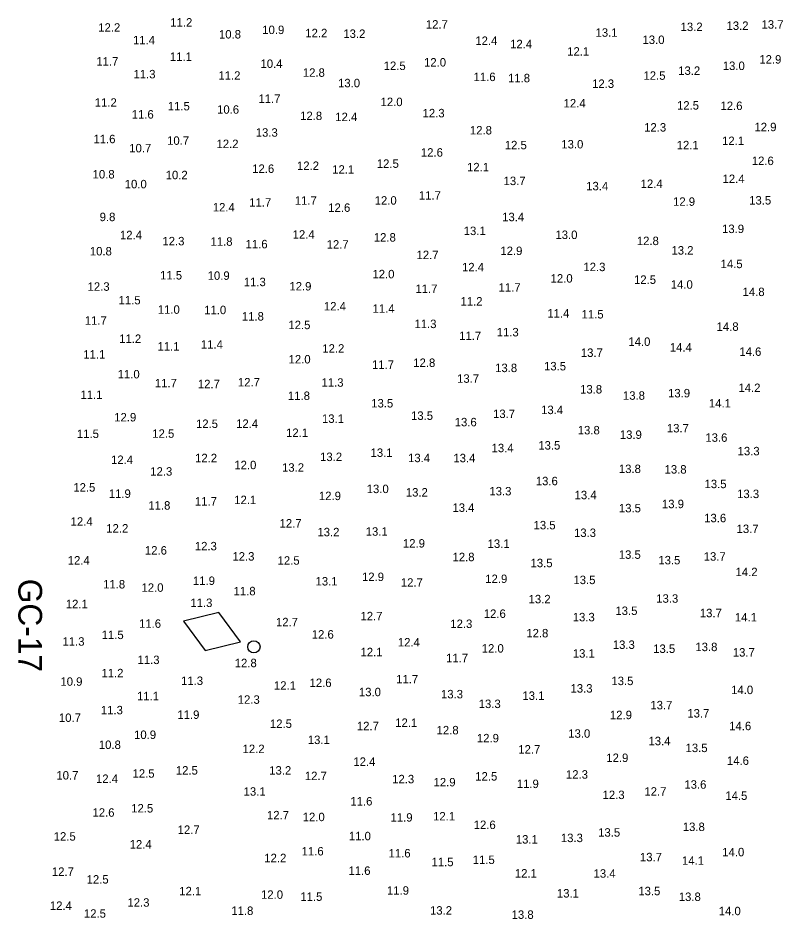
# Model space of a CAD drawing. Extents: x 1023796 to 1112670, y 656573 to 837340.
# Drawn here: x 1109618 to 1110070, y 667529 to 668062 of the extents above; entities that cross this region are included whole.
import ezdxf

# ---------------------------------------------------------------- set-up
doc = ezdxf.new("R2010")
doc.units = 0
doc.layers.add('V-CHAN-NAID', color=7, linetype='Continuous')
doc.layers.add('V-TOPO-SOUN', color=7, linetype='Continuous')

msp = doc.modelspace()

# ---------------------------------------------------------------- linework, layer by layer
at = {"layer": 'V-CHAN-NAID'}
msp.add_lwpolyline([(1109749.49, 667692.55), (1109736.68, 667709.99), (1109715.66, 667704.87), (1109728.47, 667687.43)], close=True, dxfattribs=at)
msp.add_circle((1109757.38, 667689.68), 3.6, dxfattribs=at)

# ---------------------------------------------------------------- texts
msp.add_text('GC-17', height=14, rotation=270, dxfattribs=at).set_placement((1109618.13, 667729.94))
at = {"layer": 'V-TOPO-SOUN'}
for s, p in [('11.2 ', (1109707.94, 668056.45)), ('12.2 ', (1109665.36, 668053.43)), ('10.9 ', (1109762.3, 668052.03)), ('12.7 ', (1109859, 668055.25)), ('13.2 ', (1110009.59, 668053.81)), ('13.2 ', (1110036.74, 668054.49)), ('13.7 ', (1110057.43, 668055.22)), ('11.4 ', (1109685.89, 668045.99)), ('10.8 ', (1109736.72, 668049.41)), ('12.2 ', (1109787.75, 668050.15)), ('13.2 ', (1109810.23, 668049.75)), ('12.4 ', (1109888.25, 668045.6)), ('13.1 ', (1109959.31, 668050.44)), ('13.0 ', (1109987.07, 668046.17)), ('12.4 ', (1109908.82, 668043.64)), ('11.1 ', (1109707.72, 668036.19)), ('12.1 ', (1109942.55, 668039.26)), ('11.7 ', (1109664.22, 668033.38)), ('10.4 ', (1109761.27, 668032.02)), ('12.5 ', (1109834.08, 668030.77)), ('12.0 ', (1109857.93, 668032.84)), ('13.0 ', (1110034.52, 668030.77)), ('12.9 ', (1110056.13, 668034.56)), ('11.3 ', (1109686.17, 668025.83)), ('11.2 ', (1109736.39, 668025.03)), ('12.8 ', (1109786.28, 668026.77)), ('12.5 ', (1109987.64, 668024.99)), ('13.2 ', (1110008.17, 668027.91)), ('13.0 ', (1109807.1, 668020.57)), ('11.6 ', (1109887.21, 668024.23)), ('11.8 ', (1109907.58, 668023.52)), ('12.3 ', (1109957.28, 668020.18)), ('11.2 ', (1109663.28, 668009.06)), ('11.7 ', (1109760.04, 668011.33)), ('12.0 ', (1109832.25, 668009.43)), ('12.4 ', (1109940.45, 668008.64)), ('11.5 ', (1109706.44, 668006.91)), ('10.6 ', (1109735.6, 668004.93)), ('12.5 ', (1110007.46, 668007.36)), ('12.6 ', (1110033.16, 668007.12)), ('11.6 ', (1109685.13, 668002.04)), ('12.8 ', (1109784.68, 668001.18)), ('12.4 ', (1109805.48, 668000.56)), ('12.3 ', (1109857.08, 668002.79)), ('12.8 ', (1109885.05, 667992.66)), ('12.3 ', (1109988.04, 667994.38)), ('12.9 ', (1110053.25, 667994.59)), ('11.6 ', (1109662.51, 667987.49)), ('13.3 ', (1109758.46, 667991.34)), ('10.7 ', (1109683.69, 667982.08)), ('10.7 ', (1109706.05, 667986.55)), ('12.2 ', (1109735.26, 667984.61)), ('12.5 ', (1109905.66, 667983.89)), ('13.0 ', (1109939.08, 667984.4)), ('12.1 ', (1110007.28, 667983.88)), ('12.1 ', (1110034.09, 667986.39)), ('12.6 ', (1109856.07, 667979.54)), ('12.2 ', (1109782.83, 667971.68)), ('12.5 ', (1109830.01, 667972.93)), ('12.6 ', (1110051.66, 667974.57)), ('10.8 ', (1109662.03, 667966.63)), ('10.2 ', (1109705.22, 667966.2)), ('12.6 ', (1109756.36, 667969.93)), ('12.1 ', (1109803.65, 667969.46)), ('12.1 ', (1109883.35, 667970.85)), ('10.0 ', (1109681.01, 667960.82)), ('13.7 ', (1109904.95, 667962.72)), ('12.4 ', (1109985.98, 667961.02)), ('12.4 ', (1110034.38, 667963.94)), ('13.4 ', (1109953.8, 667959.63)), ('11.7 ', (1109754.59, 667949.96)), ('11.7 ', (1109781.53, 667951.07)), ('12.0 ', (1109828.75, 667951.15)), ('11.7 ', (1109854.87, 667954.12)), ('12.9 ', (1110005.13, 667950.47)), ('13.5 ', (1110050.11, 667951.24)), ('12.4 ', (1109733.05, 667947.12)), ('12.6 ', (1109801.33, 667946.91)), ('9.8', (1109666.18, 667941.4)), ('13.4 ', (1109904.11, 667941.39)), ('13.9 ', (1110034.11, 667934.36)), ('12.4 ', (1109678.2, 667930.73)), ('12.4 ', (1109780.27, 667931.03)), ('12.8 ', (1109828.24, 667929.32)), ('13.1 ', (1109881.39, 667933.17)), ('13.0 ', (1109935.61, 667930.84)), ('12.3 ', (1109703.28, 667927.09)), ('11.8 ', (1109731.71, 667926.85)), ('11.6 ', (1109752.45, 667925.34)), ('12.7 ', (1109800.37, 667925.16)), ('12.8 ', (1109983.72, 667927.24)), ('10.8 ', (1109660.37, 667921.13)), ('12.7 ', (1109853.49, 667918.93)), ('12.9 ', (1109903.06, 667921.35)), ('13.2 ', (1110004.2, 667921.64)), ('14.5 ', (1110033.25, 667913.63)), ('12.0 ', (1109827.43, 667907.6)), ('12.4 ', (1109880.37, 667911.72)), ('12.3 ', (1109952.13, 667911.84)), ('11.5 ', (1109701.9, 667906.91)), ('10.9 ', (1109730.03, 667906.71)), ('11.3 ', (1109751.36, 667902.96)), ('12.0 ', (1109932.76, 667905.07)), ('12.5 ', (1109982.06, 667904.33)), ('12.3 ', (1109659.06, 667900.24)), ('12.9 ', (1109778.35, 667900.41)), ('11.7 ', (1109852.85, 667898.93)), ('11.7 ', (1109902, 667899.71)), ('14.0 ', (1110003.77, 667901.45)), ('14.8 ', (1110046.24, 667897.1)), ('11.5 ', (1109677.38, 667892.2)), ('11.2 ', (1109879.5, 667891.51)), ('11.0 ', (1109700.54, 667886.64)), ('11.0 ', (1109727.98, 667886.4)), ('12.4 ', (1109798.74, 667888.59)), ('11.4 ', (1109827.51, 667887.24)), ('11.8 ', (1109750.25, 667882.62)), ('11.4 ', (1109930.82, 667884.4)), ('11.5 ', (1109951.08, 667883.86)), ('11.7 ', (1109657.38, 667880.14)), ('12.5 ', (1109777.75, 667877.54)), ('11.3 ', (1109852.27, 667878.17)), ('14.8 ', (1110030.88, 667876.54)), ('11.7 ', (1109878.7, 667871.08)), ('11.3 ', (1109900.89, 667873.26)), ('11.2 ', (1109677.73, 667869.4)), ('11.1 ', (1109700.36, 667864.87)), ('11.4 ', (1109726.02, 667866)), ('14.0 ', (1109978.71, 667867.66)), ('11.1 ', (1109656.52, 667860.13)), ('12.2 ', (1109797.8, 667863.63)), ('13.7 ', (1109950.63, 667861.11)), ('14.4 ', (1110003.23, 667864.3)), ('14.6 ', (1110044.32, 667861.74)), ('12.0 ', (1109777.88, 667857.26)), ('11.7 ', (1109827.19, 667854.06)), ('12.8 ', (1109851.57, 667855.19)), ('13.8 ', (1109899.96, 667852.14)), ('13.5 ', (1109928.86, 667853.15)), ('11.0 ', (1109676.83, 667848.41)), ('12.7 ', (1109747.91, 667843.66)), ('11.3 ', (1109797.32, 667843.49)), ('13.7 ', (1109877.46, 667845.82)), ('11.7 ', (1109698.83, 667843.12)), ('12.7 ', (1109724.24, 667842.63)), ('13.8 ', (1109950.18, 667839.49)), ('14.2 ', (1110043.78, 667840.36)), ('11.1 ', (1109654.84, 667836.25)), ('11.8 ', (1109777.48, 667835.66)), ('13.8 ', (1109975.5, 667835.79)), ('13.9 ', (1110002.19, 667837.19)), ('13.5 ', (1109826.71, 667831.23)), ('13.4 ', (1109927.14, 667827.31)), ('14.1 ', (1110026.34, 667831.22)), ('12.9 ', (1109674.79, 667822.97)), ('13.1 ', (1109797.61, 667822.12)), ('13.5 ', (1109850.25, 667823.9)), ('13.7 ', (1109898.73, 667824.98)), ('12.5 ', (1109723.13, 667819.1)), ('12.4 ', (1109746.86, 667819.18)), ('13.6 ', (1109876.07, 667820.08)), ('13.7 ', (1110001.47, 667816.48)), ('11.5 ', (1109652.76, 667813.17)), ('12.5 ', (1109697.3, 667813.31)), ('12.1 ', (1109776.38, 667813.78)), ('13.8 ', (1109948.8, 667815.31)), ('13.9 ', (1109973.66, 667812.67)), ('13.5 ', (1109925.49, 667806.32)), ('13.6 ', (1110024.24, 667810.93)), ('13.1 ', (1109826.32, 667802.01)), ('13.4 ', (1109897.85, 667804.78)), ('13.3 ', (1110043.29, 667802.93)), ('12.4 ', (1109672.92, 667797.81)), ('12.2 ', (1109722.59, 667798.86)), ('13.2 ', (1109796.47, 667799.54)), ('13.4 ', (1109848.49, 667798.89)), ('13.4 ', (1109875.28, 667798.83)), ('12.3 ', (1109696.1, 667790.9)), ('12.0 ', (1109745.79, 667794.73)), ('13.2 ', (1109773.99, 667793.24)), ('13.8 ', (1109973.1, 667792.45)), ('13.8 ', (1110000.12, 667792.13)), ('13.6 ', (1109923.99, 667785.23)), ('12.5 ', (1109650.62, 667781.47)), ('13.0 ', (1109824.04, 667780.59)), ('13.3 ', (1109896.57, 667779.23)), ('13.5 ', (1110023.73, 667783.52)), ('11.9 ', (1109671.59, 667777.77)), ('12.1 ', (1109745.74, 667774.07)), ('12.9 ', (1109795.79, 667776.45)), ('13.2 ', (1109847.18, 667778.56)), ('13.4 ', (1109946.93, 667776.97)), ('13.3 ', (1110043, 667777.64)), ('11.8 ', (1109694.97, 667770.82)), ('11.7 ', (1109722.52, 667773.25)), ('13.4 ', (1109874.72, 667769.51)), ('13.5 ', (1109973.12, 667769.22)), ('13.9 ', (1109998.58, 667771.68)), ('13.6 ', (1110023.53, 667763.36)), ('12.4 ', (1109649.03, 667761.3)), ('12.7 ', (1109772.53, 667760.25)), ('13.5 ', (1109922.68, 667759.15)), ('12.2 ', (1109670.11, 667757.28)), ('13.2 ', (1109794.92, 667755.05)), ('13.1 ', (1109823.45, 667755.39)), ('13.3 ', (1109946.58, 667754.64)), ('13.7 ', (1110042.69, 667756.97)), ('12.9 ', (1109845.45, 667748.37)), ('13.1 ', (1109895.51, 667748.17)), ('12.6 ', (1109692.94, 667744.24)), ('12.3 ', (1109722.44, 667746.73)), ('12.4 ', (1109647.32, 667738.36)), ('12.3 ', (1109744.67, 667740.67)), ('12.5 ', (1109771.37, 667738.26)), ('12.8 ', (1109874.78, 667740.33)), ('13.5 ', (1109920.89, 667736.76)), ('13.5 ', (1109973.04, 667741.73)), ('13.5 ', (1109996.44, 667738.45)), ('13.7 ', (1110023.26, 667740.63)), ('14.2 ', (1110042.09, 667731.48)), ('11.9 ', (1109721.33, 667726.28)), ('13.1 ', (1109793.78, 667725.96)), ('12.9 ', (1109821.26, 667728.58)), ('12.9 ', (1109894.12, 667727.41)), ('13.5 ', (1109946.24, 667726.78)), ('11.8 ', (1109668.23, 667724.2)), ('12.0 ', (1109690.91, 667722.22)), ('12.7 ', (1109844.22, 667725.23)), ('11.8 ', (1109745.35, 667720.16)), ('13.2 ', (1109919.74, 667715.42)), ('13.3 ', (1109995.19, 667715.76)), ('12.1 ', (1109646.17, 667712.52)), ('11.3 ', (1109719.81, 667713.22)), ('12.7 ', (1109820.36, 667705.36)), ('12.6 ', (1109893.24, 667706.8)), ('13.3 ', (1109945.84, 667704.77)), ('13.5 ', (1109971.06, 667708.51)), ('13.7 ', (1110020.96, 667707.18)), ('14.1 ', (1110041.71, 667704.68)), ('11.6 ', (1109689.47, 667700.93)), ('12.7 ', (1109770.41, 667701.83)), ('12.3 ', (1109873.47, 667700.81)), ('11.5 ', (1109667.38, 667694.28)), ('12.6 ', (1109791.56, 667694.54)), ('12.8 ', (1109918.4, 667695.27)), ('11.3 ', (1109644.2, 667690.35)), ('12.4 ', (1109842.45, 667689.89)), ('12.1 ', (1109820.39, 667684.11)), ('12.0 ', (1109892.04, 667686.28)), ('13.1 ', (1109945.87, 667683.29)), ('13.3 ', (1109969.51, 667688.45)), ('13.5 ', (1109993.39, 667686.07)), ('13.8 ', (1110018.33, 667687.14)), ('13.7 ', (1110040.45, 667683.93)), ('11.3 ', (1109688.57, 667679.5)), ('11.7 ', (1109870.96, 667680.6)), ('12.8 ', (1109746.02, 667677.65)), ('11.2 ', (1109667.25, 667671.67)), ('11.7 ', (1109841.46, 667668.06)), ('10.9 ', (1109642.99, 667666.66)), ('11.3 ', (1109714.31, 667667.13)), ('12.1 ', (1109769.22, 667664.33)), ('12.6 ', (1109790.26, 667665.93)), ('13.3 ', (1109944.52, 667662.62)), ('13.5 ', (1109968.69, 667667.04)), ('11.1 ', (1109688.26, 667658.09)), ('13.0 ', (1109819.44, 667660.49)), ('13.3 ', (1109867.95, 667659.21)), ('13.1 ', (1109916.08, 667658.31)), ('14.0 ', (1110039.47, 667661.72)), ('12.3 ', (1109747.8, 667656)), ('13.3 ', (1109890.26, 667653.48)), ('13.7 ', (1109991.73, 667652.72)), ('11.3 ', (1109666.91, 667649.77)), ('11.9 ', (1109712.14, 667647.07)), ('12.9 ', (1109967.83, 667646.91)), ('13.7 ', (1110013.59, 667647.9)), ('10.7 ', (1109642.1, 667645.27)), ('12.5 ', (1109766.85, 667641.72)), ('12.1 ', (1109840.91, 667642.32)), ('12.7 ', (1109818.23, 667640.37)), ('12.8 ', (1109865.36, 667637.93)), ('13.0 ', (1109943.18, 667635.93)), ('14.6 ', (1110038.32, 667640.41)), ('10.9 ', (1109686.53, 667635.21)), ('13.1 ', (1109789.22, 667632.19)), ('12.9 ', (1109889.18, 667633.19)), ('13.4 ', (1109990.61, 667631.51)), ('10.8 ', (1109665.7, 667629.29)), ('12.2 ', (1109750.67, 667626.85)), ('12.7 ', (1109913.66, 667626.58)), ('13.5 ', (1110012.51, 667627.44)), ('12.9 ', (1109965.68, 667621.58)), ('14.6 ', (1110037, 667619.88)), ('12.5 ', (1109711.21, 667614.13)), ('13.2 ', (1109766.42, 667614.12)), ('12.4 ', (1109816.16, 667619.3)), ('10.7 ', (1109640.61, 667611.22)), ('12.4 ', (1109664.01, 667609.2)), ('12.5 ', (1109685.63, 667612.3)), ('12.7 ', (1109787.48, 667610.87)), ('12.3 ', (1109839.09, 667608.98)), ('12.5 ', (1109888.23, 667610.61)), ('12.3 ', (1109941.82, 667611.72)), ('12.9 ', (1109863.55, 667607.15)), ('11.9 ', (1109912.77, 667606.17)), ('13.6 ', (1110011.83, 667605.78)), ('13.1 ', (1109751.29, 667601.65)), ('12.3 ', (1109963.47, 667599.66)), ('12.7 ', (1109988.19, 667601.67)), ('14.5 ', (1110036.04, 667599.17)), ('11.6 ', (1109814.4, 667595.86)), ('12.6 ', (1109661.94, 667589.23)), ('12.5 ', (1109684.84, 667591.73)), ('12.7 ', (1109765.09, 667587.66)), ('12.0 ', (1109786.21, 667586.59)), ('11.9 ', (1109838.13, 667586.31)), ('12.1 ', (1109863.28, 667587)), ('12.7 ', (1109712.29, 667579.06)), ('12.6 ', (1109887.3, 667581.94)), ('13.5 ', (1109960.86, 667577.42)), ('13.8 ', (1110010.89, 667580.76)), ('12.5 ', (1109639.02, 667575.09)), ('11.0 ', (1109813.5, 667575.3)), ('13.1 ', (1109912.17, 667573.34)), ('13.3 ', (1109938.81, 667574.21)), ('12.4 ', (1109683.93, 667570.42)), ('11.6 ', (1109785.59, 667566.33)), ('12.2 ', (1109763.51, 667562.35)), ('11.6 ', (1109836.97, 667565.14)), ('11.5 ', (1109886.71, 667561.27)), ('13.7 ', (1109985.56, 667562.87)), ('14.0 ', (1110034.23, 667565.81)), ('11.5 ', (1109862.33, 667559.97)), ('14.1 ', (1110010.41, 667560.79)), ('12.7 ', (1109637.94, 667554.27)), ('11.6 ', (1109813.26, 667554.84)), ('12.1 ', (1109911.61, 667553.27)), ('13.4 ', (1109958.14, 667553.16)), ('12.5 ', (1109658.49, 667549.68)), ('12.1 ', (1109713.24, 667542.75)), ('12.0 ', (1109761.57, 667540.68)), ('11.9 ', (1109836.03, 667543.12)), ('13.1 ', (1109936.47, 667541.46)), ('13.5 ', (1109984.61, 667542.79)), ('12.4 ', (1109636.74, 667534.16)), ('12.3 ', (1109682.6, 667536.01)), ('11.5 ', (1109784.82, 667539.48)), ('13.8 ', (1110008.52, 667539.4)), ('12.5 ', (1109656.89, 667529.5)), ('11.8 ', (1109744.03, 667531.14)), ('13.2 ', (1109861.46, 667531.32)), ('13.8 ', (1109909.72, 667528.83)), ('14.0 ', (1110032.14, 667530.98))]:
    msp.add_text(s, height=5, dxfattribs=at).set_placement(p)

doc.saveas('drawing.dxf')
